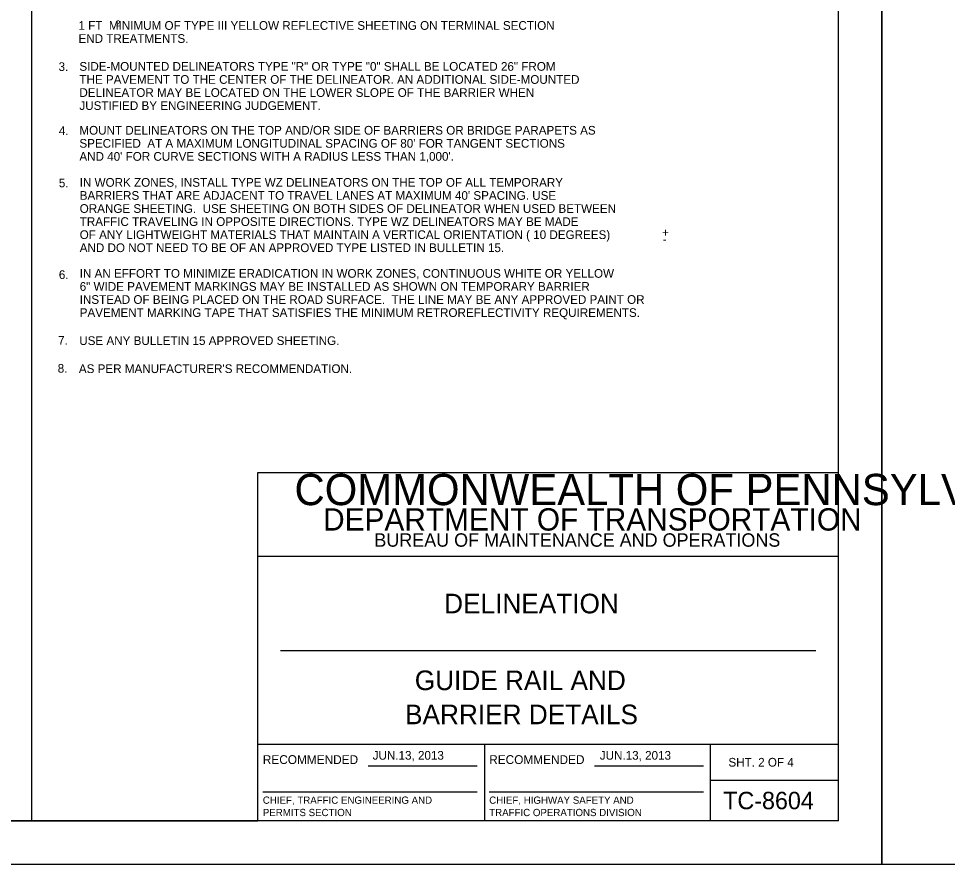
# Model space of a CAD drawing. Extents: x 640253 to 641999, y 298458 to 299646.
# Drawn here: x 640796.8 to 641116.9, y 298457.6 to 298748.9 of the extents above; entities that cross this region are included whole.
import ezdxf

# ---------------------------------------------------------------- set-up
doc = ezdxf.new("R2010")
doc.units = 0
for name, color, linetype in [('1', 7, 'Continuous'), ('2', 7, 'Continuous'), ('Level 1', 7, 'Continuous'), ('PLT-BNDY', 7, 'Continuous')]:
    doc.layers.add(name, color=color, linetype=linetype)

msp = doc.modelspace()

# ---------------------------------------------------------------- linework, layer by layer
at = {"layer": '1'}
for p, q in [((640801.38, 298472.63), (640801.38, 299036.63)), ((641079.31, 298472.63), (641079.31, 299036.63)), ((640879.31, 298472.63), (640879.31, 298592.63)), ((640879.31, 298592.63), (641079.31, 298592.63)), ((641079.31, 298563.63), (640879.31, 298563.63)), ((640887.06, 298531.31), (641071.56, 298531.31)), ((640879.31, 298499), (641079.31, 298499)), ((640957.31, 298499), (640957.31, 298472.63)), ((641035.19, 298472.63), (641035.19, 298499)), ((640917.24, 298491.57), (640954.87, 298491.57)), ((640995.24, 298491.57), (641032.87, 298491.57)), ((641035.19, 298486.63), (641079.31, 298486.63)), ((641079.31, 298472.63), (640293.31, 298472.63)), ((640293.31, 298472.63), (640879.31, 298472.63))]:
    msp.add_line(p, q, dxfattribs=at)
at = {"layer": 'Level 1'}
for p, q in [((640880.99, 298482.68), (640954.87, 298482.68)), ((640958.99, 298482.68), (641032.87, 298482.68))]:
    msp.add_line(p, q, dxfattribs=at)
at = {"layer": 'PLT-BNDY'}
for points in [[(640253.31, 299051.63), (641094.31, 299051.63), (641094.31, 298457.63), (640253.31, 298457.63)], [(641094.31, 299051.63), (641935.31, 299051.63), (641935.31, 298457.63), (641094.31, 298457.63)]]:
    msp.add_lwpolyline(points, close=True, dxfattribs=at)

# ---------------------------------------------------------------- texts
at = {"layer": '1'}
for s, height, p in [('COMMONWEALTH OF PENNSYLVANIA', 10.7828, (640891.9, 298581.36)), ('DEPARTMENT OF TRANSPORTATION', 7.6837, (640901.76, 298572.61)), ('BUREAU OF MAINTENANCE AND OPERATIONS', 4.6253, (640919.41, 298567.04)), ('DELINEATION', 6.75, (640943.46, 298544.1)), ('GUIDE RAIL AND', 6.75, (640933.34, 298517.66)), ('BARRIER DETAILS', 6.75, (640929.99, 298505.91)), ('JUN.13, 2013', 3, (640918.84, 298493.69)), ('JUN.13, 2013', 3, (640997.09, 298493.69)), ('RECOMMENDED', 3.048, (640880.99, 298492.2)), ('RECOMMENDED', 3.048, (640958.99, 298492.2)), ('SHT. 2 OF 4', 3, (641041.4, 298491.31)), ('TC-8604', 6, (641039.6, 298476.63))]:
    msp.add_text(s, height=height, dxfattribs=at).set_placement(p)
at = {"layer": '2'}
for s, height, p in [('1 FT  MINIMUM OF TYPE III YELLOW REFLECTIVE SHEETING ON TERMINAL SECTION', 3, (640817.48, 298745.07)), ('2', 2, (640830.37, 298746.32)), ('END TREATMENTS.', 3, (640817.48, 298740.57)), ('3.', 3, (640810.61, 298730.89)), ('SIDE-MOUNTED DELINEATORS TYPE "R" OR TYPE "0" SHALL BE LOCATED 26" FROM', 3, (640817.79, 298730.97)), ('THE PAVEMENT TO THE CENTER OF THE DELINEATOR. AN ADDITIONAL SIDE-MOUNTED ', 3, (640817.79, 298726.47)), ('DELINEATOR MAY BE LOCATED ON THE LOWER SLOPE OF THE BARRIER WHEN ', 3, (640817.79, 298721.97)), ('JUSTIFIED BY ENGINEERING JUDGEMENT.', 3, (640817.79, 298717.47)), ('4.', 3, (640810.71, 298708.82)), ('MOUNT DELINEATORS ON THE TOP AND/OR SIDE OF BARRIERS OR BRIDGE PARAPETS AS ', 3, (640817.79, 298708.97)), ("SPECIFIED  AT A MAXIMUM LONGITUDINAL SPACING OF 80' FOR TANGENT SECTIONS ", 3, (640817.79, 298704.47)), ("AND 40' FOR CURVE SECTIONS WITH A RADIUS LESS THAN 1,000'.", 3, (640817.79, 298699.97)), ('5.', 3, (640810.71, 298690.84)), ('IN WORK ZONES, INSTALL TYPE WZ DELINEATORS ON THE TOP OF ALL TEMPORARY', 3, (640817.9, 298691.02)), ("BARRIERS THAT ARE ADJACENT TO TRAVEL LANES AT MAXIMUM 40' SPACING. USE", 3, (640817.9, 298686.52)), ('ORANGE SHEETING.  USE SHEETING ON BOTH SIDES OF DELINEATOR WHEN USED BETWEEN', 3, (640817.9, 298682.02)), ('TRAFFIC TRAVELING IN OPPOSITE DIRECTIONS. TYPE WZ DELINEATORS MAY BE MADE', 3, (640817.9, 298677.52)), ('OF ANY LIGHTWEIGHT MATERIALS THAT MAINTAIN A VERTICAL ORIENTATION ( 10 DEGREES) ', 3, (640817.9, 298673.02)), ('AND DO NOT NEED TO BE OF AN APPROVED TYPE LISTED IN BULLETIN 15.', 3, (640817.9, 298668.52)), ('6.', 3, (640810.71, 298659.24)), ('IN AN EFFORT TO MINIMIZE ERADICATION IN WORK ZONES, CONTINUOUS WHITE OR YELLOW ', 3, (640817.9, 298659.68)), ('6" WIDE PAVEMENT MARKINGS MAY BE INSTALLED AS SHOWN ON TEMPORARY BARRIER ', 3, (640817.9, 298655.18)), ('INSTEAD OF BEING PLACED ON THE ROAD SURFACE.  THE LINE MAY BE ANY APPROVED PAINT OR ', 3, (640817.9, 298650.68)), ('PAVEMENT MARKING TAPE THAT SATISFIES THE MINIMUM RETROREFLECTIVITY REQUIREMENTS.', 3, (640817.9, 298646.18)), ('USE ANY BULLETIN 15 APPROVED SHEETING.', 3, (640817.75, 298636.52)), ("AS PER MANUFACTURER'S RECOMMENDATION.", 3, (640817.61, 298626.86))]:
    msp.add_text(s, height=height, dxfattribs=at).set_placement(p)
for s, p in [('+', (641018.54, 298673.75)), ('-', (641018.75, 298671.51)), ('7.', (640810.47, 298636.64)), ('8.', (640810.32, 298626.98))]:
    msp.add_text(s, height=3, rotation=360, dxfattribs=at).set_placement(p)
at = {"layer": 'Level 1'}
for s, p in [('CHIEF, TRAFFIC ENGINEERING AND', (640880.99, 298478.51)), ('CHIEF, HIGHWAY SAFETY AND', (640958.99, 298478.51)), ('PERMITS SECTION', (640880.99, 298474.26)), ('TRAFFIC OPERATIONS DIVISION', (640958.99, 298474.26))]:
    msp.add_text(s, height=2.5, dxfattribs=at).set_placement(p)

doc.saveas('drawing.dxf')
